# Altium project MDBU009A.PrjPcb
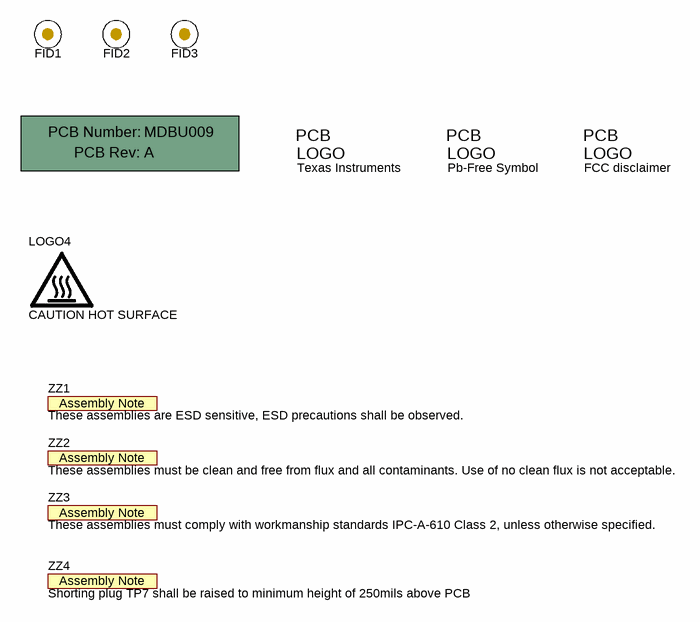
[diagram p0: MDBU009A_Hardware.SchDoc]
CopyrightYear: 2015; PCB_Layout: Rick Duncan; PCB_Rev: A; PRJ_Customer: Public Release; PRJ_Engineer: Rick Duncan; PRJ_Number: MDBU009; PRJ_Title: DRV8885EVM; SCH_Rev: A; TechSupport: http://www.ti.com/support; TID: N/A
3 sheets, 60 parts. Net scope: global (net labels, ports and power ports of the same name join across sheets).
Board file: MDBU009A.PcbDoc
Sheets:
  MDBU009A_Hardware.SchDoc
  MDBU009A_MSP430F2617.SchDoc
  MDBU009A.SchDoc

## Sheet MDBU009A_Hardware.SchDoc
size 431 x 279 mm; Date: Not shown in title block; ApprovedBy: Not shown in title block; CheckedBy: Not shown in title block; Author: Not shown in title block; CompanyName: Not shown in title block; Engineer: Not shown in title block; Organization: Not shown in title block; Address1: Not shown in title block; Address2: Not shown in title block; Address3: Not shown in title block; Address4: Not shown in title block; DocumentNumber: 1; Revision: Use project parameter SCH_Rev; SheetNumber: 3; SheetTotal: 3; PageSetup: Record=PageOptions¦CenterHorizontal=True¦CenterVertical=True¦PrintScale=1.00¦XCorrection=1.00¦YCorrection=1.00¦PrintKind=0¦BorderSize=5000000¦LeftOffset=0¦BottomOffset=0¦Orientation=2¦PaperLength=1000¦PaperWidth=1000¦Scale=100¦PaperSource=15¦PrintQuality=600¦MediaType=1¦DitherType=10¦PaperKind=Letter¦PrintScaleMode=1

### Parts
!PCB1  Printed Circuit Board  (value not drawn)  (mechanical)
FID1  Fiducial  [Fiducial10-20]  (value not drawn)
FID2  Fiducial  [Fiducial10-20]  (value not drawn)
FID3  Fiducial  [Fiducial10-20]  (value not drawn)
Logo1  Texas Instruments  [TI_Stacked_Overlay_Small_Vertical]  (no BOM)
Logo2  Pb-Free Symbol  [Pb-Free_Overlay_Small]  (no BOM)
Logo3  FCC disclaimer  [FCC_disclaimer_stacked]  (no BOM)
LOGO4  CAUTION HOT SURFACE  [IEC_HotSurface_Small]  (no BOM)
ZZ1  These assemblies are ESD sensitive, ESD precautions shall be observed.  [AssemblyNote]  (no BOM)
ZZ2  These assemblies must be clean and free from flux and all contaminants. Use of no clean flux is not acceptable.  [AssemblyNote]  (no BOM)
ZZ3  These assemblies must comply with workmanship standards IPC-A-610 Class 2, unless otherwise specified.  [AssemblyNote]  (no BOM)
ZZ4  Shorting plug TP7 shall be raised to minimum height of 250mils above PCB  [AssemblyNote]  (no BOM)

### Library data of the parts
!PCB1 = PCB: Manufacturer: Any; PartNumber: MDBU009; SymbolCreator: a0412235
FID1-FID3 = Fiducial: Fiducial mark.  There is nothing to buy or mount.; SymbolCreator: codlsc
Logo1 = TI_Logo: Texas Instrument Corporate Signature; SymbolCreator: a0412235
Logo2 = Pb-Free: SymbolCreator: a0412235
Logo3 = FCC_disclaimer: SymbolCreator: codlsc
LOGO4 = IEC_HotSurface: IEC 61010-1 Hot Surface Warning; SymbolCreator: a0412235
ZZ1-ZZ4 = AssemblyNote: SymbolCreator: codlsc

## Sheet MDBU009A_MSP430F2617.SchDoc
size 431 x 279 mm; Date: Not shown in title block; ApprovedBy: Not shown in title block; CheckedBy: Not shown in title block; Author: Not shown in title block; CompanyName: Not shown in title block; Engineer: Not shown in title block; Organization: Not shown in title block; Address1: Not shown in title block; Address2: Not shown in title block; Address3: Not shown in title block; Address4: Not shown in title block; DocumentNumber: 1; Revision: Use project parameter SCH_Rev; SheetNumber: 2; SheetTotal: 3; PageSetup: Record=PageOptions¦CenterHorizontal=True¦CenterVertical=True¦PrintScale=1.00¦XCorrection=1.00¦YCorrection=1.00¦PrintKind=0¦BorderSize=5000000¦LeftOffset=0¦BottomOffset=0¦Orientation=2¦PaperLength=1000¦PaperWidth=1000¦Scale=100¦PaperSource=15¦PrintQuality=600¦MediaType=1¦DitherType=10¦PrintScaleMode=1¦PaperKind=Letter
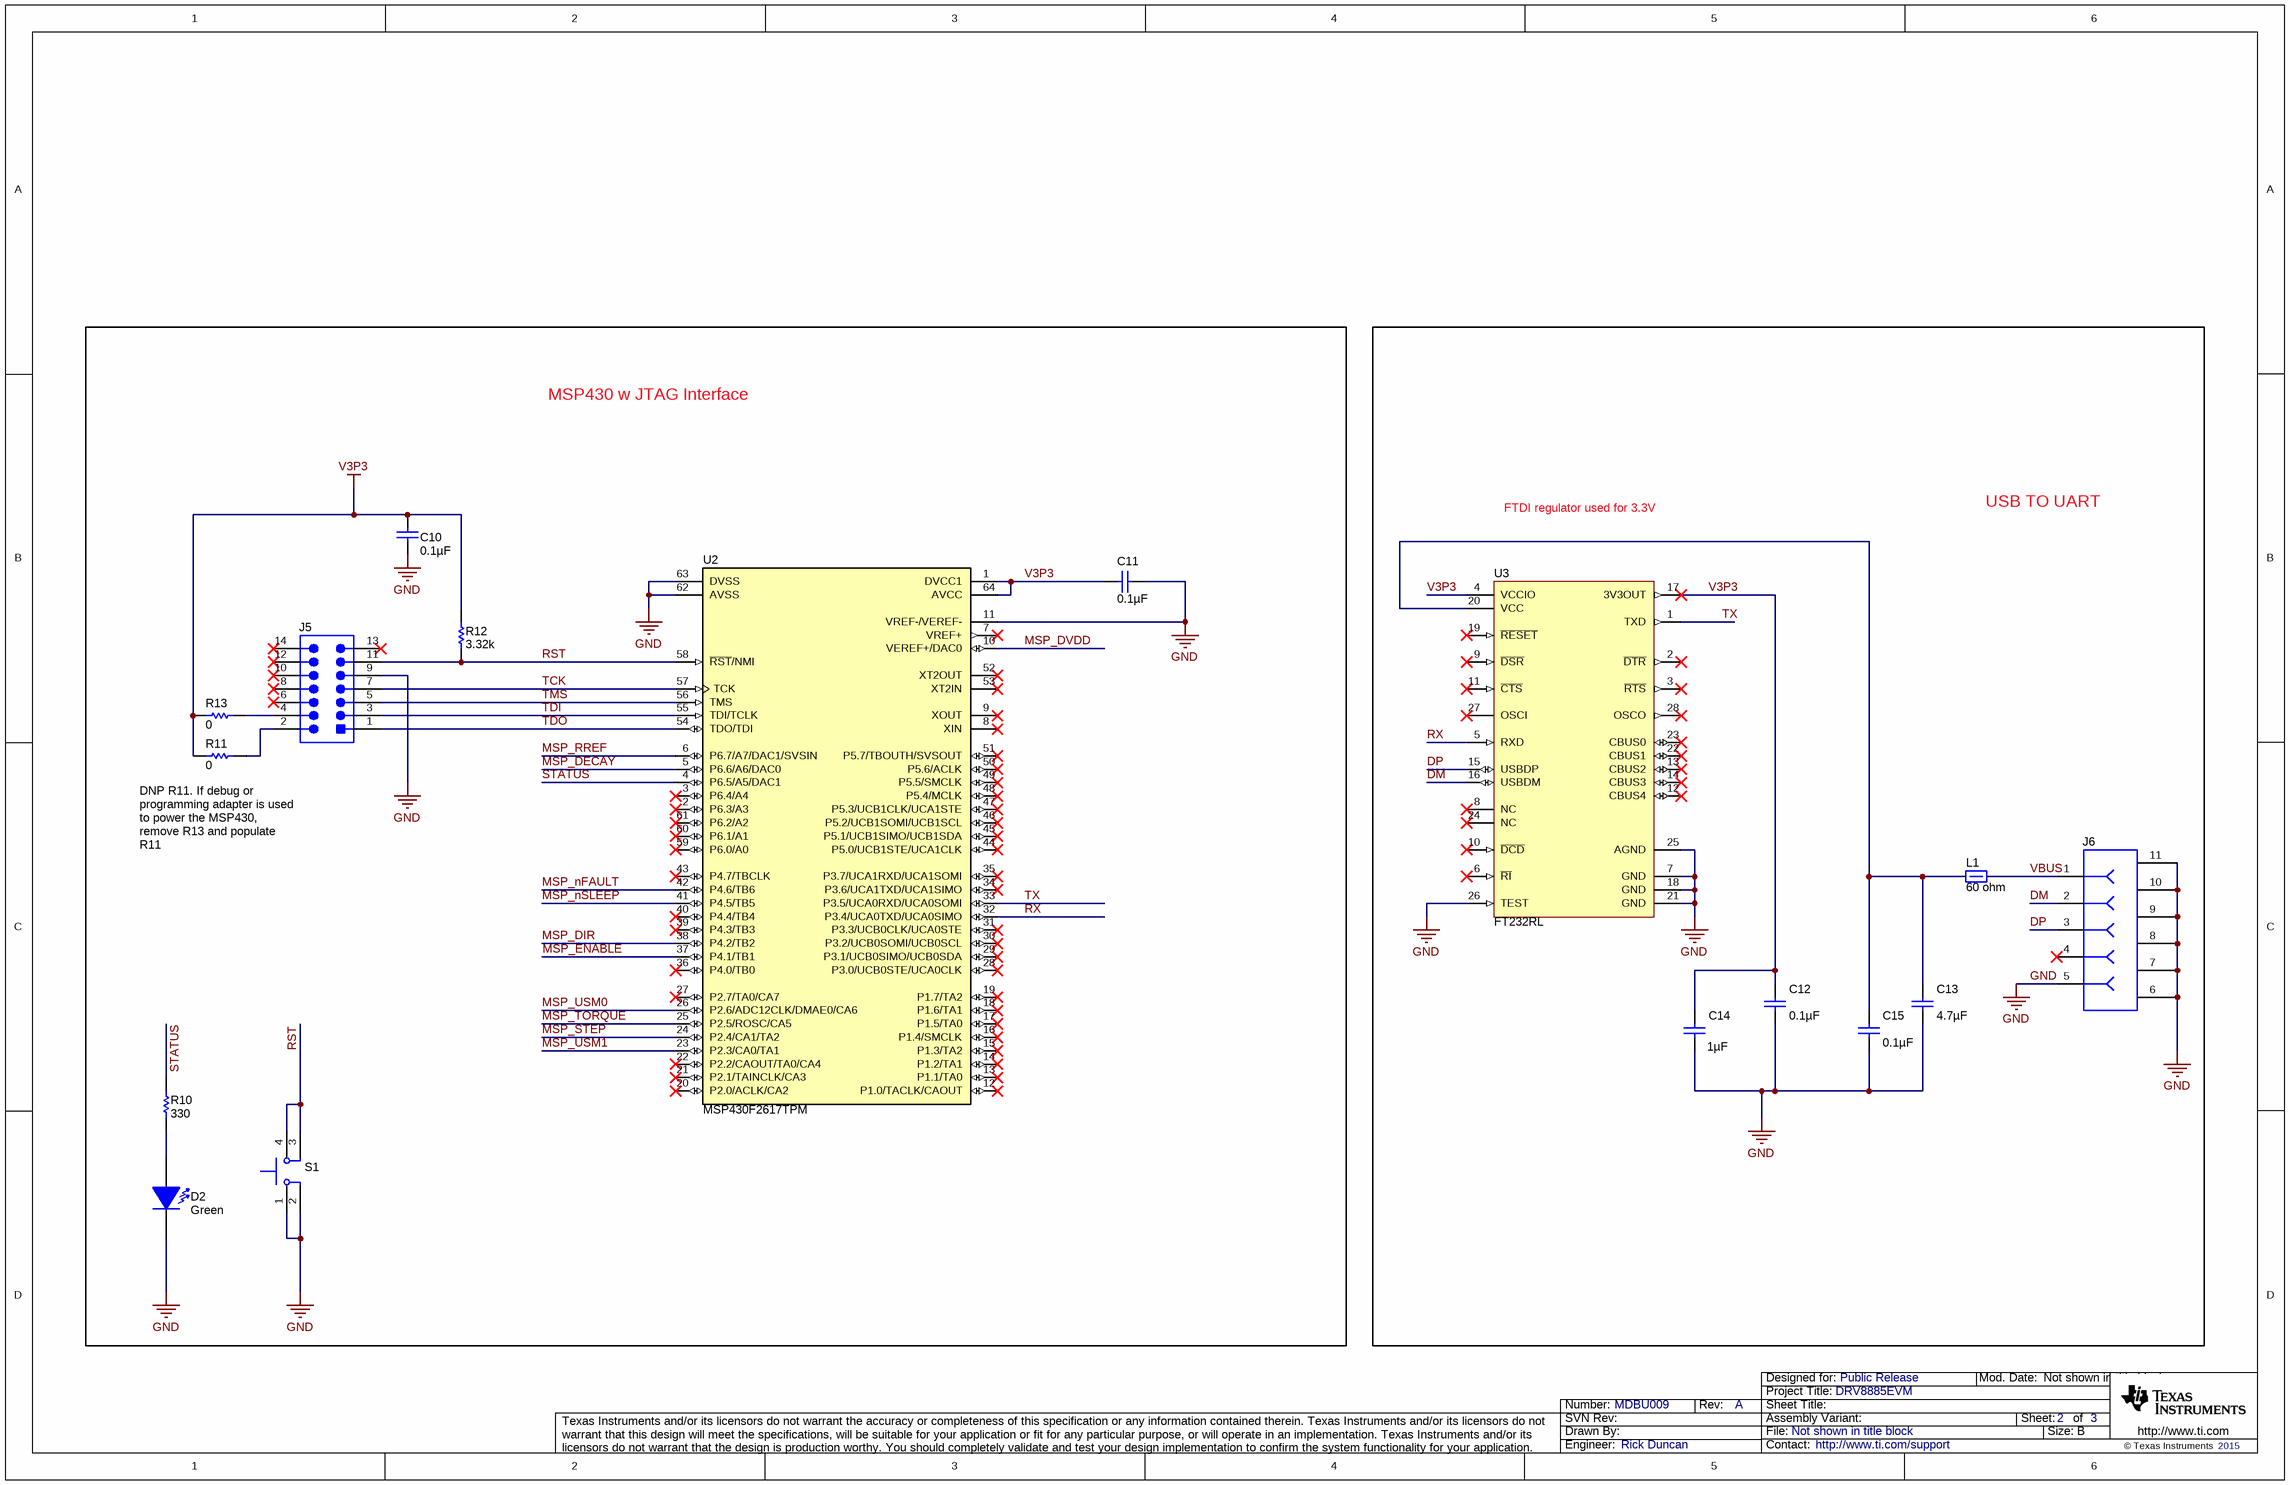
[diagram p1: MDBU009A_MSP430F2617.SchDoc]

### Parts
C10  ValueDisplayed: 0.1µF  [0402L]  (hidden comment: GRM155R61A104KA01D)
C11  ValueDisplayed: 0.1µF  [0402L]  (hidden comment: GRM155R61A104KA01D)
C12  ValueDisplayed: 0.1µF  [0402L]  (hidden comment: GRM155R61A104KA01D)
C13  ValueDisplayed: 4.7µF  [0603L]  (hidden comment: CGB3B1X5R1A475K055AC)
C14  ValueDisplayed: 1µF  [0402L]  (hidden comment: GRM155R61A105KE15D)
C15  ValueDisplayed: 0.1µF  [0402L]  (hidden comment: GRM155R61A104KA01D)
D2  value Green  [LED_LTST-C190]  (hidden comment: LTST-C190GKT)
J5  PEC07DAAN  [CONN_PEC07DAAN]  (value not drawn)
J6  ZX62-B-5PA(11)  [CONN_USB_micro_ZX62-B-5PA]  (value not drawn)
L1  value 60 ohm  [0805L]  (hidden comment: BKP2125HS600-T)
R10  value 330  [0402L]  (hidden comment: CRCW0402330RJNED)
R11  value 0  [0402L]  (hidden comment: ERJ-2GE0R00X)
R12  value 3.32k  [0402L]  (hidden comment: CRCW04023K32FKED)
R13  value 0  [0402L]  (hidden comment: ERJ-2GE0R00X)
S1  EVQP1D05M  [SW_EVQxxx05M]  (value not drawn)
U2  MSP430F2617TPM  [PM0064A_N]
U3  FT232RL  [SSOP28_N]

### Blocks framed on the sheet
MSP430 w JTAG Interface: C10 C11 D2 J5 R10-R13 S1 U2
USB TO UART: C12-C15 J6 L1 U3

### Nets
GND: C10.2 C11.2 C12.2 C13.2 C14.2 C15.2 D2.2(K) J5.9 J6.5 J6.6 J6.7 J6.8 J6.9 J6.10 J6.11 S1.1 S1.2 U2.11(VREF-/VEREF-) U2.62(AVSS) U2.63(DVSS) U3.7(GND) U3.18(GND) U3.21(GND) U3.25(AGND) U3.26(TEST)
V3P3: C10.1 C11.1 C12.1 C14.1 R11.1 R12.2 R13.1 U2.1(DVCC1) U2.64(AVCC) U3.4(VCCIO) U3.17(3V3OUT)
DM: J6.2 U3.16(USBDM)
DP: J6.3 U3.15(USBDP)
MSP_DECAY: U2.5(P6.6/A6/DAC0)
MSP_DIR: U2.38(P4.2/TB2)
MSP_DVDD: U2.10(VEREF+/DAC0)
MSP_ENABLE: U2.37(P4.1/TB1)
MSP_nFAULT: U2.42(P4.6/TB6)
MSP_nSLEEP: U2.41(P4.5/TB5)
MSP_RREF: U2.6(P6.7/A7/DAC1/SVSIN)
MSP_STEP: U2.24(P2.4/CA1/TA2)
MSP_TORQUE: U2.25(P2.5/ROSC/CA5)
MSP_USM0: U2.26(P2.6/ADC12CLK/DMAE0/CA6)
MSP_USM1: U2.23(P2.3/CA0/TA1)
RST: J5.11 R12.1 S1.3 S1.4 U2.58(~{RST}/NMI)
RX: U2.32(P3.4/UCA0TXD/UCA0SIMO) U3.5(RXD)
STATUS: R10.2 U2.4(P6.5/A5/DAC1)
TCK: J5.7 U2.57(TCK)
TDI: J5.3 U2.55(TDI/TCLK)
TDO: J5.1 U2.54(TDO/TDI)
TMS: J5.5 U2.56(TMS)
TX: U2.33(P3.5/UCA0RXD/UCA0SOMI) U3.1(TXD)
VBUS: J6.1 L1.2
NetC13_1: C13.1 C15.1 L1.1 U3.20(VCC)
NetD2_1: D2.1(A) R10.1
NetJ5_2: J5.2 R11.2
NetJ5_4: J5.4 R13.2

Not connected (* = marked no-connect by the designer): J5 6* 8* 10* 12* 13* 14*; J6 4*; U2 2(P6.3/A3)* 3(P6.4/A4)* 7(VREF+)* 8(XIN)* 9(XOUT)* 12(P1.0/TACLK/CAOUT)* 13(P1.1/TA0)* 14(P1.2/TA1)* 15(P1.3/TA2)* 16(P1.4/SMCLK)* 17(P1.5/TA0)* 18(P1.6/TA1)* 19(P1.7/TA2)* 20(P2.0/ACLK/CA2)* 21(P2.1/TAINCLK/CA3)* 22(P2.2/CAOUT/TA0/CA4)* 27(P2.7/TA0/CA7)* 28(P3.0/UCB0STE/UCA0CLK)* 29(P3.1/UCB0SIMO/UCB0SDA)* 30(P3.2/UCB0SOMI/UCB0SCL)* 31(P3.3/UCB0CLK/UCA0STE)* 34(P3.6/UCA1TXD/UCA1SIMO)* 35(P3.7/UCA1RXD/UCA1SOMI)* 36(P4.0/TB0)* 39(P4.3/TB3)* 40(P4.4/TB4)* 43(P4.7/TBCLK)* 44(P5.0/UCB1STE/UCA1CLK)* 45(P5.1/UCB1SIMO/UCB1SDA)* 46(P5.2/UCB1SOMI/UCB1SCL)* 47(P5.3/UCB1CLK/UCA1STE)* 48(P5.4/MCLK)* 49(P5.5/SMCLK)* 50(P5.6/ACLK)* 51(P5.7/TBOUTH/SVSOUT)* 52(XT2OUT)* 53(XT2IN)* 59(P6.0/A0)* 60(P6.1/A1)* 61(P6.2/A2)*; U3 2(~{DTR})* 3(~{RTS})* 6(~{RI})* 8(NC)* 9(~{DSR})* 10(~{DCD})* 11(~{CTS})* 12(CBUS4)* 13(CBUS2)* 14(CBUS3)* 19(~{RESET})* 22(CBUS1)* 23(CBUS0)* 24(NC)* 27(OSCI)* 28(OSCO)*

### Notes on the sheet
- FTDI regulator used for 3.3V
- (near R11) DNP R11. If debug or programming adapter is used to power the MSP430, remove R13 and populate R11

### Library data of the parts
C10-C12 C15 = GRM155R61A104KA01D: CAP, CERM, 0.1uF, 10V, +/-10%, X5R, 0402; Manufacturer: MuRata; Polarized: N; CompType: Capacitor; U/M: EA; Cap_F: 0.0000001; Tolerance_%: 10; Value1: Unknown; TaMin_C: -55; TaMax_C: 85; Cap_Case: 0402
C13 = CGB3B1X5R1A475K055AC: CAP, CERM, 4.7uF, 10V, +/-10%, X5R, 0603; Manufacturer: TDK; Polarized: N; CompType: Capacitor; U/M: EA; Cap_F: 0.0000047; Tolerance_%: 10; Value1: Unknown; TaMin_C: -55; TaMax_C: 85; Cap_Case: 0603
C14 = GRM155R61A105KE15D: CAP, CERM, 1uF, 10V, +/-10%, X5R, 0402; Manufacturer: MuRata; Polarized: N; CompType: Capacitor; U/M: EA; Cap_F: 0.000001; Tolerance_%: 10; Value1: Unknown; TaMin_C: -55; TaMax_C: 85; Cap_Case: 0402
D2 = LTST-C190GKT: LED, Green, SMD; Manufacturer: Lite-On; Vf_V: 2.1; Value2: 2.1V; Io_A: 0.02; Power_TotalModule: 0.1; Value1: 0.1W; U/M: EA
J5 = PEC07DAAN: Header, 100mil, 7x2, Tin plated, TH; Manufacturer: Sullins Connector Solutions; SymbolCreator: a0412235; U/M: EA
J6 = ZX62-B-5PA(11): Connector, micro USB Type B, Receptacle, R/A, SMD; Manufacturer: Hirose Electric Co. Ltd.; SymbolCreator: a0411947; U/M: EA
L1 = BKP2125HS600-T: Ferrite Bead, 60 ohm @ 100 MHz, 3 A, 0805; Manufacturer: Taiyo Yuden; Imax_A: 3; DCR_ohm: 0.025; Value1: 0.025 ohm; Value2: 3A; ZTyp@100MHz_Ohm: 60
R10 = CRCW0402330RJNED: RES, 330 ohm, 5%, 0.063W, 0402; Manufacturer: Vishay-Dale; CompType: Resistor; Value_Code: 330R; Tolerance_%: 5; Power_W: 0.063; VDC_V: 50; TempCo: 200 ppm/C; EIA_Code: E24; U/M: EA
R11 R13 = ERJ-2GE0R00X: RES, 0 ohm, 5%, 0.063W, 0402; Manufacturer: Panasonic; CompType: Resistor; Value_Code: 0000; Tolerance_%: 5; Power_W: 0.063; VDC_V: 50; TempCo: 600 ppm/C; EIA_Code: E24; U/M: EA
R12 = CRCW04023K32FKED: RES, 3.32k ohm, 1%, 0.063W, 0402; Manufacturer: Vishay-Dale; CompType: Resistor; Res_ohm: 3320; Value_Code: 3k32; Tolerance_%: 1; Power_W: 0.063; VDC_V: 50; TempCo: 100 ppm/C; EIA_Code: E96; U/M: EA
S1 = EVQP1D05M: Switch, Tactile, SPST-NO, 0.05A, 12V, SMT; Manufacturer: Panasonic; SymbolCreator: a0799628; VDC_V: 12; SwitchFunction: Off-Mom; PositionCount: 1; CurrentRating_mA: 50
U2 = MSP430F2617TPM: 16 MHz Mixed Signal Microcontroller with 92 KB Flash, 8192 B SRAM and 48 GPIOs, -40 to 105 degC, 64-pin QFP (PM), Green (RoHS & no Sb/Br); Manufacturer: Texas Instruments; Alternate PartNumber: Equivalent; ADC: 12-bit SAR; ADC Channels: 8; Brown Out Reset: Yes; DMA: 3; Flash(KB): 92; Frequency(MHz): 16; GPIO: 48; Multiplier: 16x16; Pin/Package: 64LQFP; SRAM(B): 8192; SubFamily: 2 Series, Extended Temp; Timers - 16-bit: 2
U3 = FT232RL: USB to Serial UART, SSOP28; Manufacturer: FTDI; SymbolCreator: x0208326

## Sheet MDBU009A.SchDoc
size 431 x 279 mm; Date: Not shown in title block; ApprovedBy: Not shown in title block; CheckedBy: Not shown in title block; Author: Not shown in title block; CompanyName: Not shown in title block; Engineer: Not shown in title block; Organization: Not shown in title block; Address1: Not shown in title block; Address2: Not shown in title block; Address3: Not shown in title block; Address4: Not shown in title block; DocumentNumber: 1; Revision: Use project parameter SCH_Rev; SheetNumber: 1; SheetTotal: 3; PageSetup: Record=PageOptions¦CenterHorizontal=True¦CenterVertical=True¦PrintScale=1.00¦XCorrection=1.00¦YCorrection=1.00¦PrintKind=0¦BorderSize=5000000¦LeftOffset=0¦BottomOffset=0¦Orientation=2¦PaperLength=1000¦PaperWidth=1000¦Scale=100¦PaperSource=15¦PrintQuality=600¦MediaType=1¦DitherType=10¦PaperKind=Letter¦PrintScaleMode=1
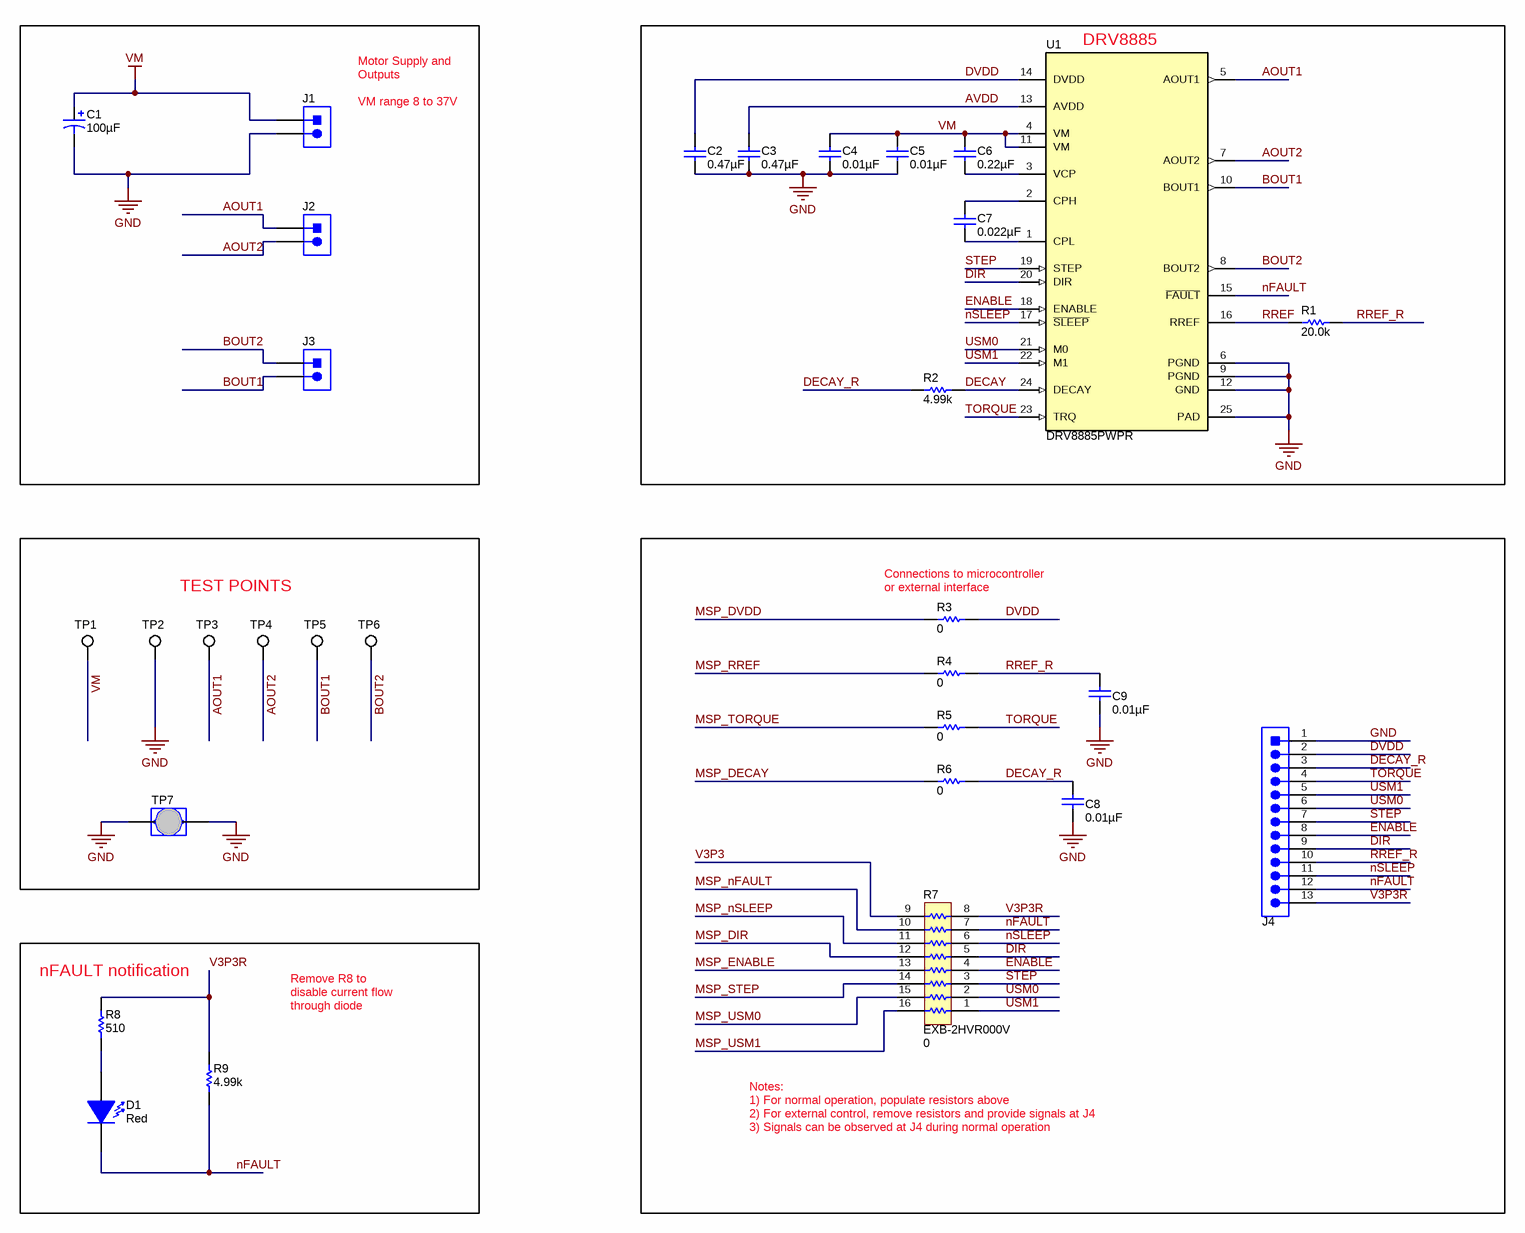
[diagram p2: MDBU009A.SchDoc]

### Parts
C1  ValueDisplayed: 100µF  [SM_RADIAL_F]  (hidden comment: EEE-FK1H101P)
C2  ValueDisplayed: 0.47µF  [0603L]  (hidden comment: C0603C474K9RACTU)
C3  ValueDisplayed: 0.47µF  [0603L]  (hidden comment: C0603C474K9RACTU)
C4  ValueDisplayed: 0.01µF  [0805L]  (hidden comment: C2012X7R2A103K)
C5  ValueDisplayed: 0.01µF  [0805L]  (hidden comment: C2012X7R2A103K)
C6  ValueDisplayed: 0.22µF  [0603L]  (hidden comment: GRM188R71E224KA88D)
C7  ValueDisplayed: 0.022µF  [0603L]  (hidden comment: C1608X7R2A223K)
C8  ValueDisplayed: 0.01µF  [0402L]  (hidden comment: GRM155R71E103KA01D)
C9  ValueDisplayed: 0.01µF  [0402L]  (hidden comment: GRM155R71E103KA01D)
D1  value Red  [LED_LTST-C190_Red]  (hidden comment: LTST-C190CKT)
J1  ED555/2DS  [TERM_BLK_ED555-2DS]  (value not drawn)
J2  ED555/2DS  [TERM_BLK_ED555-2DS]  (value not drawn)
J3  ED555/2DS  [TERM_BLK_ED555-2DS]  (value not drawn)
J4  TSW-113-07-G-S  [TSW-113-07-G-S]  (value not drawn)
R1  ValueDisplayed: 20.0k  [0402L]  (hidden comment: CRCW040220K0FKED)
R2  value 4.99k  [0402L]  (hidden comment: CRCW04024K99FKED)
R3  ValueDisplayed: 0  [0402L]  (hidden comment: ERJ-2GE0R00X)
R4  ValueDisplayed: 0  [0402L]  (hidden comment: ERJ-2GE0R00X)
R5  ValueDisplayed: 0  [0402L]  (hidden comment: ERJ-2GE0R00X)
R6  ValueDisplayed: 0  [0402L]  (hidden comment: ERJ-2GE0R00X)
R7  EXB-2HVR000V  ValueDisplayed: 0  [RESCAXS_EXB-2HV]
R8  value 510  [0402L]  (hidden comment: CRCW0402510RJNED)
R9  value 4.99k  [0402L]  (hidden comment: CRCW04024K99FKED)
TP1  5016  [Testpoint_Keystone_Compact]  (value not drawn)
TP2  5016  [Testpoint_Keystone_Compact]  (value not drawn)
TP3  5016  [Testpoint_Keystone_Compact]  (value not drawn)
TP4  5016  [Testpoint_Keystone_Compact]  (value not drawn)
TP5  5016  [Testpoint_Keystone_Compact]  (value not drawn)
TP6  5016  [Testpoint_Keystone_Compact]  (value not drawn)
TP7  D3082-05  [Harwin_D3082-05]  (value not drawn)
U1  DRV8885PWPR  [PWP0024B_N]

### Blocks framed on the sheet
DRV8885: C2-C7 R1 R2 U1
TEST POINTS: TP1-TP7
nFAULT notification: D1 R8 R9

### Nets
GND: C1.2(-) C2.1 C3.1 C4.1 C5.1 C8.2 C9.2 J1.2 J4.1 TP2.1 TP7.1 TP7.2 U1.6(PGND) U1.9(PGND) U1.12(GND) U1.25(PAD)
V3P3: R7.9
VM: C1.1(+) C4.2 C5.2 C6.1 J1.1 TP1.1 U1.4(VM) U1.11(VM)
AOUT1: J2.1 TP3.1 U1.5(AOUT1)
AOUT2: J2.2 TP4.1 U1.7(AOUT2)
AVDD: C3.2 U1.13(AVDD)
BOUT1: J3.2 TP5.1 U1.10(BOUT1)
BOUT2: J3.1 TP6.1 U1.8(BOUT2)
DECAY: R2.1 U1.24(DECAY)
DECAY_R: C8.1 J4.3 R2.2 R6.1
DIR: J4.9 R7.5 U1.20(DIR)
DVDD: C2.2 J4.2 R3.1 U1.14(DVDD)
ENABLE: J4.8 R7.4 U1.18(ENABLE)
MSP_DECAY: R6.2
MSP_DIR: R7.12
MSP_DVDD: R3.2
MSP_ENABLE: R7.13
MSP_nFAULT: R7.10
MSP_nSLEEP: R7.11
MSP_RREF: R4.2
MSP_STEP: R7.14
MSP_TORQUE: R5.2
MSP_USM0: R7.15
MSP_USM1: R7.16
nFAULT: D1.2(K) J4.12 R7.7 R9.1 U1.15(~{FAULT})
nSLEEP: J4.11 R7.6 U1.17(~{SLEEP})
RREF: R1.2 U1.16(RREF)
RREF_R: C9.1 J4.10 R1.1 R4.1
STEP: J4.7 R7.3 U1.19(STEP)
TORQUE: J4.4 R5.1 U1.23(TRQ)
USM0: J4.6 R7.2 U1.21(M0)
USM1: J4.5 R7.1 U1.22(M1)
V3P3R: J4.13 R7.8 R8.2 R9.2
NetC6_2: C6.2 U1.3(VCP)
NetC7_1: C7.1 U1.2(CPH)
NetC7_2: C7.2 U1.1(CPL)
NetD1_1: D1.1(A) R8.1

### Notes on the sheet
- Motor Supply and Outputs
  VM range 8 to 37V
- (near R3) Connections to microcontroller
  or external interface
- Remove R8 to disable current flow through diode
- Notes:
  1) For normal operation, populate resistors above
  2) For external control, remove resistors and provide signals at J4
  3) Signals can be observed at J4 during normal operation

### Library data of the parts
C1 = EEE-FK1H101P: CAP, AL, 100 µF, 50 V, +/- 20%, 0.34 ohm, SMD; Manufacturer: Panasonic; Value: 100uF; Polarized: Y; CompType: Capacitor; U/M: EA; Cap_F: 0.0001; Tolerance_%: 20; ESR_ohm: 0.34; VDC_V: 50; Value2: 50V; IRMS_A: 0.35; TaMin_C: -55; TaMax_C: 105; Cap_Case: F
C2 C3 = C0603C474K9RACTU: CAP, CERM, 0.47 µF, 6.3 V, +/- 10%, X7R, 0603; Manufacturer: Kemet; Polarized: N; CompType: Capacitor; Value: 0.47uF; U/M: EA; Cap_F: 0.00000047; Tolerance_%: 10; Value1: Unknown; VDC_V: 6.3; Value2: 6.3V; TaMin_C: -55; TaMax_C: 125; Cap_Case: 0603
C4 C5 = C2012X7R2A103K: CAP, CERM, 0.01 µF, 100 V, +/- 10%, X7R, 0805; Manufacturer: TDK; Polarized: N; CompType: Capacitor; Value: 0.01uF; U/M: EA; Cap_F: 0.00000001; Tolerance_%: 10; ESR_ohm: 0.0571; Value1: 0.0571 ohm; VDC_V: 100; Value2: 100V; TaMin_C: -55; TaMax_C: 125; Cap_Case: 0805
C6 = GRM188R71E224KA88D: CAP, CERM, 0.22 µF, 25 V, +/- 10%, X7R, 0603; Manufacturer: MuRata; Polarized: N; CompType: Capacitor; Value: 0.22uF; U/M: EA; Cap_F: 0.00000022; Tolerance_%: 10; Value1: Unknown; VDC_V: 25; Value2: 25V; TaMin_C: -55; TaMax_C: 125; Cap_Case: 0603
C7 = C1608X7R2A223K: CAP, CERM, 0.022 µF, 100 V, +/- 10%, X7R, 0603; Manufacturer: TDK; Polarized: N; CompType: Capacitor; Value: 0.022uF; U/M: EA; Cap_F: 0.000000022; Tolerance_%: 10; ESR_ohm: 0.037; Value1: 0.037 ohm; VDC_V: 100; Value2: 100V; TaMin_C: -55; TaMax_C: 125; Cap_Case: 0603
C8 C9 = GRM155R71E103KA01D: CAP, CERM, 0.01 µF, 25 V, +/- 10%, X7R, 0402; Manufacturer: MuRata; Value: 0.01uF; Polarized: N; CompType: Capacitor; U/M: EA; Cap_F: 0.00000001; Tolerance_%: 10; Value1: Unknown; VDC_V: 25; Value2: 25V; TaMin_C: -55; TaMax_C: 125; Cap_Case: 0402
D1 = LTST-C190CKT: LED, Red, SMD; Manufacturer: Lite-On; Vf_V: 2; Value2: 2V; Io_A: 0.02; Tjmax_C: 85; Power_TotalModule: 0.0625; Value1: 0.0625W; U/M: EA
J1-J3 = ED555/2DS: Terminal Block, 6A, 3.5mm Pitch, 2-Pos, TH; Manufacturer: On-Shore Technology; SymbolCreator: a0412235; CompType: Connector; U/M: EA
J4 = TSW-113-07-G-S: Header, 100mil, 13x1, Gold, TH; Manufacturer: Samtec; SymbolCreator: a0411947; U/M: EA
R1 = CRCW040220K0FKED: RES, 20.0 k, 1%, 0.063 W, 0402; Manufacturer: Vishay-Dale; CompType: Resistor; Res_ohm: 20000; Value_Code: 20k0; Tolerance_%: 1; Power_W: 0.063; Value2: 0.063W; VDC_V: 50; TempCo: 100 ppm/C; EIA_Code: E96; U/M: EA; Value: 20.0k
R2 R9 = CRCW04024K99FKED: RES, 4.99k ohm, 1%, 0.063W, 0402; Manufacturer: Vishay-Dale; CompType: Resistor; Res_ohm: 4990; Value_Code: 4k99; Tolerance_%: 1; Power_W: 0.063; VDC_V: 50; TempCo: 100 ppm/C; EIA_Code: E96; U/M: EA
R3-R6 = ERJ-2GE0R00X: RES, 0, 5%, 0.063 W, 0402; Manufacturer: Panasonic; CompType: Resistor; Value_Code: 0000; Tolerance_%: 5; Power_W: 0.063; Value2: 0.063W; VDC_V: 50; TempCo: 600 ppm/C; EIA_Code: E24; U/M: EA; Value: 0
R7 = EXB-2HVR000V: RES, 0, 5%, 0.0625 W, Resistor Array - 8x1; Manufacturer: Panasonic; SymbolCreator: a0411947; Value: 0; Value_Code: 0000; Tolerance_%: 5; Power_W: 0.0625; TempCo: ppm/C; EIA_Code: E24; U/M: EA
R8 = CRCW0402510RJNED: RES, 510 ohm, 5%, 0.063W, 0402; Manufacturer: Vishay-Dale; CompType: Resistor; Value_Code: 510R; Tolerance_%: 5; Power_W: 0.063; VDC_V: 50; TempCo: 200 ppm/C; EIA_Code: E24; U/M: EA
TP1-TP6 = 5016: Test Point, Compact, SMT; Manufacturer: Keystone; CompType: Test Point Loop; U/M: EA
TP7 = D3082-05: 1mm Uninsulated Shorting Plug, 10.16mm spacing, TH; Manufacturer: Harwin; SymbolCreator: a0799628; CompType: Jumper Wire; U/M: EA
U1 = DRV8885PWPR: 1.5 A Stepper Motor Driver with STEP / DIR Interface, PWP0024B; Manufacturer: Texas Instruments; SymbolCreator: Altium; CompType: IC; U/M: EA

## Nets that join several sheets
GND: MDBU009A_MSP430F2617 (25 pins), MDBU009A (16 pins)
V3P3: MDBU009A_MSP430F2617 (11 pins), MDBU009A (R7.9)
MSP_DECAY: MDBU009A_MSP430F2617 (U2.5), MDBU009A (R6.2)
MSP_DIR: MDBU009A_MSP430F2617 (U2.38), MDBU009A (R7.12)
MSP_DVDD: MDBU009A_MSP430F2617 (U2.10), MDBU009A (R3.2)
MSP_ENABLE: MDBU009A_MSP430F2617 (U2.37), MDBU009A (R7.13)
MSP_nFAULT: MDBU009A_MSP430F2617 (U2.42), MDBU009A (R7.10)
MSP_nSLEEP: MDBU009A_MSP430F2617 (U2.41), MDBU009A (R7.11)
MSP_RREF: MDBU009A_MSP430F2617 (U2.6), MDBU009A (R4.2)
MSP_STEP: MDBU009A_MSP430F2617 (U2.24), MDBU009A (R7.14)
MSP_TORQUE: MDBU009A_MSP430F2617 (U2.25), MDBU009A (R5.2)
MSP_USM0: MDBU009A_MSP430F2617 (U2.26), MDBU009A (R7.15)
MSP_USM1: MDBU009A_MSP430F2617 (U2.23), MDBU009A (R7.16)

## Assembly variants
001: not fitted FID1 FID2 FID3 R11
